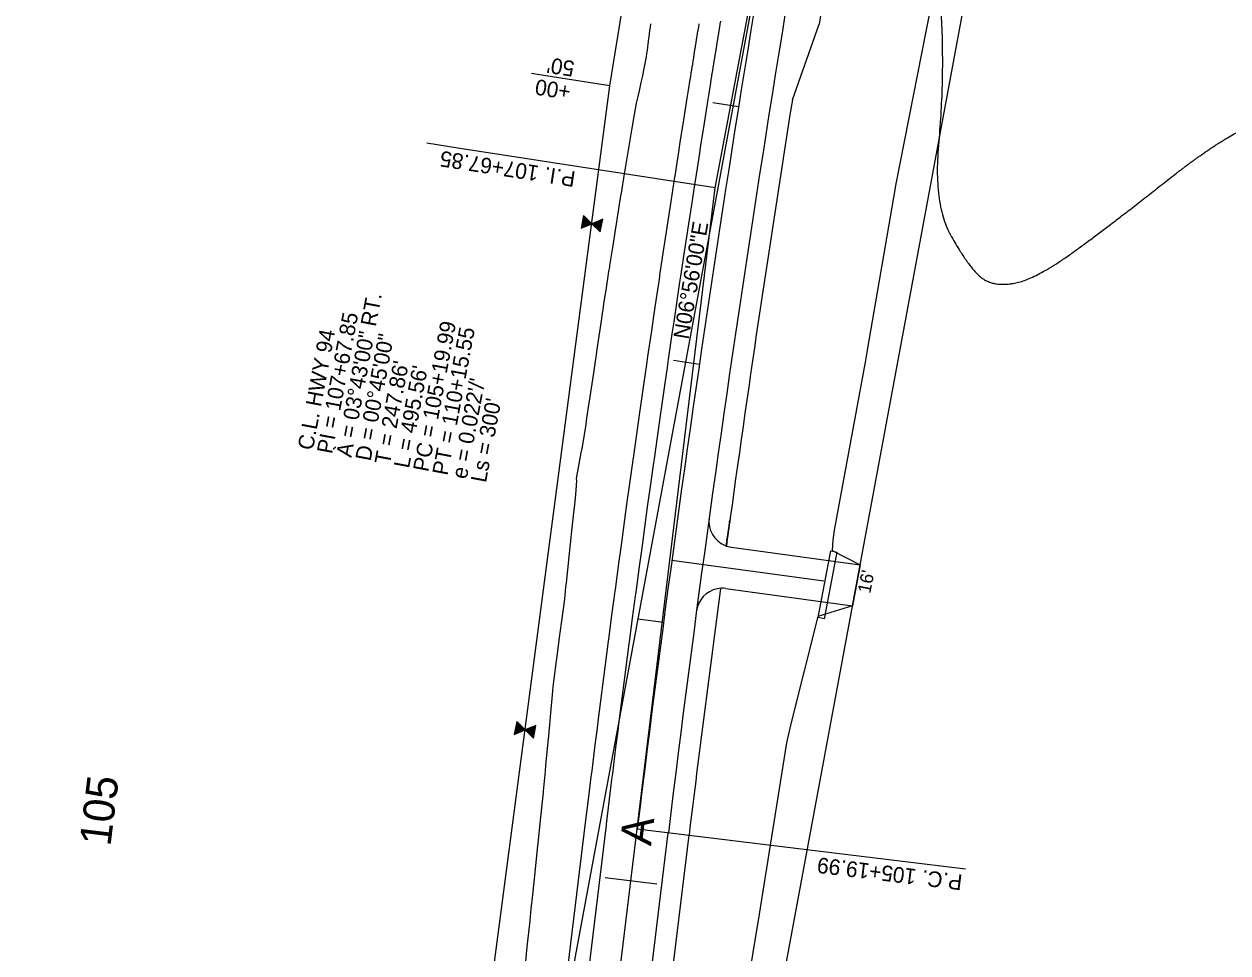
# Model space of a CAD drawing. Extents: x 674098 to 689971, y 764717 to 781049.
# Drawn here: x 688338 to 688800.2, y 765564.3 to 765920.7 of the extents above; entities that cross this region are included whole.
import ezdxf

# ---------------------------------------------------------------- set-up
doc = ezdxf.new("R2010")
doc.units = 0
for name, color, linetype in [('FLOODPLAIN', 7, 'Continuous'), ('R_Drainage Stage 2', 7, 'Continuous'), ('R_Drive Stage 2', 7, 'Continuous'), ('R_Fence', 7, 'Continuous'), ('R_Horz Alg', 7, 'Continuous'), ('R_Horz Alg Annot', 7, 'Continuous'), ('R_Horz Alg Curve Data', 7, 'Continuous'), ('R_Horz Alg Station', 7, 'Continuous'), ('R_Horz Alg Station Annot', 7, 'Continuous'), ('R_No Plot', 7, 'Continuous'), ('R_Proposed Const Limits', 7, 'Continuous'), ('R_Proposed Const Limits Stage 2', 7, 'Continuous'), ('R_Proposed Road', 7, 'Continuous'), ('R_Proposed Road S2', 7, 'Continuous'), ('R_Proposed Shoulder S1', 7, 'Continuous'), ('R_Proposed Shoulder S2', 7, 'Continuous'), ('R_ROW', 7, 'Continuous'), ('R_ROW Annot', 7, 'Continuous'), ('S_EXIST_ROW', 7, 'Continuous')]:
    doc.layers.add(name, color=color, linetype=linetype)

msp = doc.modelspace()

# ---------------------------------------------------------------- linework, layer by layer
at = {"layer": 'FLOODPLAIN'}
msp.add_open_spline([(687720.93, 765952.26), (687778.36, 766010.11), (687818.58, 766026.73), (687865.88, 766035.53), (687900.32, 766027.46), (687971.79, 766010.71), (687996.8, 765994.57), (688033.36, 766007.25), (688051.03, 766027.11), (688052.57, 766065.83), (688149.21, 766117.06), (688189.14, 766131.99), (688217.73, 766125.29), (688254.11, 766123.43), (688329.61, 766125.06), (688414.48, 766126.21), (688456.69, 766120.07), (688534.31, 766092.2), (688588.47, 766053.98), (688667.06, 766003.49), (688675.83, 765962.56), (688689.19, 765943.25), (688691.21, 765898.82), (688686.99, 765851.93), (688700.19, 765828.01), (688709.66, 765819.75), (688726.48, 765822.75), (688756.45, 765844.6), (688793.54, 765873.97), (688815.68, 765885.35), (688838.55, 765872.15), (688859.55, 765848.56), (688852.23, 765830.57), (688864.28, 765797.08), (688875.92, 765781.82), (688895.44, 765777.24), (688920.07, 765784), (688941.19, 765800.55), (688957.82, 765812.32), (689023.63, 765808.54), (689168.4, 765808.74), (689203.62, 765800.49), (689260.93, 765781.46), (689309.41, 765766.74), (689347.39, 765757.84), (689378.08, 765755.12), (689447.63, 765742.59), (689518.73, 765731.75), (689531.07, 765726.17), (689546.85, 765710.38)], degree=2, dxfattribs=at)
at = {"layer": 'R_Drainage Stage 2'}
for p, q in [((688642.8, 765692.99), (688647.71, 765718.52)), ((688645.26, 765692.51), (688650.16, 765718.05)), ((688647.71, 765718.52), (688650.16, 765718.05)), ((688645.26, 765692.51), (688642.8, 765692.99))]:
    msp.add_line(p, q, dxfattribs=at)
at = {"layer": 'R_Drive Stage 2'}
msp.add_line((688656.07, 765697.51), (688658.99, 765713.26), dxfattribs=at)
at = {"layer": 'R_Fence'}
for p, q in [((688552.01, 765843.5), (688552.55, 765842.7)), ((688552.14, 765844.2), (688553.02, 765842.89)), ((688552.28, 765844.89), (688553.49, 765843.09)), ((688552.41, 765845.59), (688553.96, 765843.28)), ((688552.55, 765846.28), (688554.43, 765843.48)), ((688552.68, 765846.97), (688554.9, 765843.68)), ((688553.74, 765846.29), (688555.37, 765843.87)), ((688555.56, 765844.5), (688555.84, 765844.07)), ((688556.32, 765844.27), (688557.37, 765842.7)), ((688556.79, 765844.46), (688559.15, 765840.95)), ((688557.26, 765844.66), (688559.29, 765841.64)), ((688557.73, 765844.85), (688559.42, 765842.34)), ((688558.2, 765845.05), (688559.56, 765843.03)), ((688558.67, 765845.25), (688559.69, 765843.73)), ((688559.14, 765845.44), (688559.83, 765844.42)), ((688559.61, 765845.64), (688559.96, 765845.11)), ((688560.08, 765845.84), (688560.1, 765845.81)), ((688551.87, 765842.81), (688552.08, 765842.5)), ((688526.51, 765649.93), (688527.39, 765648.63)), ((688526.64, 765650.62), (688527.86, 765648.82)), ((688526.78, 765651.32), (688528.33, 765649.02)), ((688526.91, 765652.01), (688528.8, 765649.21)), ((688527.05, 765652.71), (688529.27, 765649.41)), ((688528.11, 765652.03), (688529.74, 765649.61)), ((688529.92, 765650.23), (688530.21, 765649.8)), ((688530.68, 765650), (688531.73, 765648.44)), ((688531.15, 765650.19), (688533.51, 765646.68)), ((688531.62, 765650.39), (688533.65, 765647.38)), ((688532.09, 765650.59), (688533.79, 765648.07)), ((688532.56, 765650.78), (688533.92, 765648.77)), ((688533.03, 765650.98), (688534.06, 765649.46)), ((688533.5, 765651.18), (688534.19, 765650.15)), ((688533.97, 765651.37), (688534.33, 765650.85)), ((688534.45, 765651.57), (688534.46, 765651.54)), ((688526.24, 765648.54), (688526.44, 765648.23)), ((688526.37, 765649.24), (688526.91, 765648.43))]:
    msp.add_line(p, q, dxfattribs=at)
for points in [[(688555.96, 765844.12), (688555.94, 765844.12), (688552.75, 765847.28), (688551.79, 765842.38), (688555.94, 765844.11), (688555.95, 765844.11), (688559.15, 765840.94), (688560.11, 765845.85), (688555.96, 765844.12)], [(688530.32, 765649.85), (688530.3, 765649.85), (688527.11, 765653.02), (688526.15, 765648.11), (688530.3, 765649.84), (688530.32, 765649.84), (688533.51, 765646.67), (688534.47, 765651.58), (688530.32, 765649.85)]]:
    msp.add_lwpolyline(points, dxfattribs=at)
at = {"layer": 'R_Horz Alg'}
for p, q in [((688603.33, 765857.88), (688649.13, 766101.47)), ((688573.4, 765611.83), (688603.33, 765857.88)), ((688510.61, 765095.41), (688573.4, 765611.83))]:
    msp.add_line(p, q, dxfattribs=at)
msp.add_arc((696156.98, 764689.64), 7639.44, 169.35, 173.066667, dxfattribs=at)
msp.add_arc((696156.98, 764689.64), 7639.44, 169.35, 173.066667, dxfattribs=at)
at = {"layer": 'R_Horz Alg Station'}
for points in [[(688602.42, 765890.68), (688612.29, 765889.11)], [(688603.33, 765857.88), (688504.5, 765873.16), (688492.64, 765875)], [(688587.34, 765791.69), (688597.24, 765790.25)], [(688573.56, 765692.51), (688583.48, 765691.2)], [(688573.4, 765611.83), (688699.47, 765596.5)], [(688561.06, 765593.19), (688580.92, 765590.78)]]:
    msp.add_lwpolyline(points, dxfattribs=at)
at = {"layer": 'R_No Plot'}
msp.add_line((688586.66, 765714.99), (688644.96, 765707.09), dxfattribs=at)
at = {"layer": 'R_Proposed Const Limits'}
msp.add_lwpolyline([(688530.31, 765558.21), (688531.17, 765566.61), (688532.2, 765576.55), (688532.68, 765581.18), (688533.23, 765586.5), (688534.27, 765596.45), (688535.08, 765604.15), (688535.31, 765606.4), (688536.38, 765616.33), (688536.38, 765616.34), (688537.35, 765625.83), (688537.4, 765626.34), (688538.11, 765634.03), (688538.33, 765636.35), (688539.26, 765646.36), (688539.38, 765647.63), (688539.77, 765651.75), (688540.2, 765656.37), (688540.86, 765663.35), (688541.15, 765666.38), (688541.47, 765669.47), (688542.39, 765676.36), (688542.75, 765679.03), (688543.64, 765686.33), (688543.75, 765687.11), (688545.09, 765696.28), (688545.51, 765700.03), (688546.01, 765704.75), (688546.16, 765706.27), (688547.25, 765716.27), (688547.68, 765720.27), (688547.77, 765721.11), (688547.9, 765722.45), (688548.27, 765726.27), (688548.89, 765731.98), (688548.91, 765732.27), (688549.35, 765736.27), (688549.74, 765740.15), (688550.17, 765745.39), (688550.06, 765746.32), (688551.88, 765756.22), (688552.17, 765757.78), (688553.58, 765766.13), (688554.08, 765769.47), (688554.95, 765775.35), (688555.06, 765776.07), (688556.52, 765786.02), (688557.33, 765791.39), (688557.56, 765792.95), (688558, 765795.96), (688559.49, 765805.9), (688560.18, 765810.55), (688560.27, 765811.12), (688560.59, 765813.32), (688560.97, 765815.84), (688561.38, 765818.56), (688562.52, 765825.78), (688562.8, 765827.51), (688562.9, 765828.13), (688564.08, 765835.71), (688565.07, 765841.69), (688565.72, 765845.62), (688565.73, 765845.69), (688567.25, 765855.56), (688567.29, 765855.88), (688568.42, 765863.28), (688568.44, 765863.36), (688568.88, 765865.48), (688569.63, 765870.05), (688570.5, 765875.4), (688571.41, 765880.81), (688572.17, 765885.31), (688573.09, 765890.37), (688573.68, 765892.91), (688574.21, 765895.16), (688574.93, 765898.27), (688575.53, 765900.83), (688575.96, 765903.03), (688576.2, 765904.29), (688576.33, 765905), (688576.44, 765905.56), (688576.68, 765906.82), (688576.92, 765908.09), (688577.1, 765909.37), (688577.26, 765910.65), (688577.43, 765911.92), (688577.59, 765913.2), (688577.67, 765913.83), (688577.76, 765914.48), (688577.82, 765914.94), (688577.93, 765915.8), (688578.09, 765917.04), (688578.25, 765918.32), (688578.42, 765919.59), (688578.59, 765920.87)], dxfattribs=at)
at = {"layer": 'R_Proposed Const Limits Stage 2'}
msp.add_lwpolyline([(688739.6, 766170.7), (688739.78, 766170.36), (688733.09, 766125.83), (688723.38, 766100.71), (688722.97, 766099.48), (688703.6, 766016.4), (688703.35, 766015.16), (688684.44, 765919.13), (688684.2, 765917.9), (688672.72, 765859.42), (688671.72, 765854.17), (688661.69, 765795.57), (688660.89, 765791), (688648.95, 765726.45), (688648.45, 765722.64), (688648.26, 765718.66), (688658.99, 765713.26), (688656.07, 765697.51), (688642.73, 765693.37), (688632.18, 765651.68), (688630.7, 765644.89), (688619.68, 765575.99), (688618.83, 765570.71), (688614.85, 765546.36)], dxfattribs=at)
at = {"layer": 'R_Proposed Road'}
for points in [[(688561.57, 765613.69), (688562.73, 765623.22), (688563.68, 765630.86), (688563.96, 765633.16), (688565.2, 765643.1), (688565.88, 765648.45), (688566.46, 765653.03), (688567.73, 765662.97), (688568.12, 765666.03), (688569.01, 765672.9), (688570.3, 765682.83), (688570.4, 765683.61), (688571.61, 765692.76), (688572.73, 765701.18), (688572.93, 765702.69), (688574.26, 765712.62), (688575.09, 765718.75), (688575.61, 765722.54), (688576.96, 765732.47), (688577.49, 765736.31), (688578.34, 765742.39), (688579.72, 765752.31), (688579.94, 765753.87), (688581.12, 765762.23), (688582.43, 765771.42), (688582.53, 765772.14), (688583.95, 765782.05), (688584.95, 765788.97), (688585.39, 765791.97), (688586.84, 765801.88), (688587.52, 765806.51), (688588.3, 765811.79), (688589.78, 765821.69), (688590.13, 765824.04), (688590.62, 765827.35), (688591.26, 765831.6), (688592.76, 765841.5), (688592.78, 765841.57), (688594.28, 765851.4), (688595.46, 765859.09), (688595.48, 765859.17), (688595.81, 765861.3), (688597.35, 765871.19), (688597.68, 765873.31), (688598.19, 765876.6), (688598.9, 765881.09), (688600.47, 765890.98), (688600.96, 765894.11), (688601.62, 765898.2), (688601.81, 765899.38), (688602, 765900.57), (688602.04, 765900.87), (688602.19, 765901.75), (688602.38, 765902.93), (688602.57, 765904.11), (688602.76, 765905.29), (688602.95, 765906.48), (688603.14, 765907.66), (688603.33, 765908.84), (688603.52, 765910.02), (688603.64, 765910.76), (688603.71, 765911.2), (688603.77, 765911.61), (688603.9, 765912.39), (688604.09, 765913.57), (688604.28, 765914.75), (688604.47, 765915.93), (688604.67, 765917.11), (688604.86, 765918.29), (688605.05, 765919.48), (688605.24, 765920.65), (688605.24, 765920.66), (688605.44, 765921.84)], [(688499.6, 765096.98), (688510.82, 765196.35), (688553.07, 765543.79), (688561.52, 765613.28), (688561.57, 765613.69)]]:
    msp.add_lwpolyline(points, dxfattribs=at)
msp.add_arc((696156.98, 764689.64), 7627.44, 169.35, 173.066667, dxfattribs=at)
at = {"layer": 'R_Proposed Road S2'}
for p, q in [((688609.56, 765719.96), (688658.99, 765713.26)), ((688607.41, 765704.11), (688656.07, 765697.51))]:
    msp.add_line(p, q, dxfattribs=at)
msp.add_lwpolyline([(688522.17, 765094.24), (688534.59, 765193.47), (688585.28, 765610.38)], dxfattribs=at)
for centre, start, end in [((688610.9, 765729.87), 172.1512, 247.63), ((688610.9, 765729.87), 247.63, 262.2866), ((688606.07, 765694.2), 101.9504, 172.422), ((688606.07, 765694.2), 82.2866, 101.9504)]:
    msp.add_arc(centre, 10, start, end, dxfattribs=at)
at = {"layer": 'R_Proposed Shoulder S1'}
msp.add_line((688632.95, 765891.66), (688643.22, 765920.72), dxfattribs=at)
msp.add_lwpolyline([(688545.12, 765544.76), (688553.57, 765614.24), (688554.79, 765624.2), (688555.73, 765631.84), (688556.02, 765634.15), (688557.26, 765644.1), (688557.93, 765649.45), (688558.52, 765654.04), (688559.78, 765663.99), (688560.18, 765667.05), (688561.07, 765673.93), (688562.36, 765683.87), (688562.46, 765684.65), (688563.67, 765693.81), (688564.79, 765702.24), (688564.99, 765703.75), (688566.32, 765713.69), (688567.16, 765719.83), (688567.67, 765723.63), (688569.03, 765733.56), (688569.56, 765737.41), (688570.4, 765743.49), (688571.79, 765753.42), (688572.01, 765754.99), (688573.19, 765763.35), (688574.5, 765772.55), (688574.6, 765773.28), (688576.03, 765783.2), (688577.03, 765790.12), (688577.46, 765793.12), (688578.92, 765803.04), (688579.6, 765807.68), (688580.38, 765812.96), (688581.86, 765822.88), (688582.21, 765825.23), (688582.71, 765828.54), (688583.35, 765832.79), (688584.85, 765842.71), (688584.86, 765842.77), (688586.36, 765852.62), (688587.55, 765860.31), (688587.56, 765860.39), (688587.89, 765862.52), (688589.44, 765872.43), (688589.77, 765874.55), (688590.28, 765877.84), (688590.99, 765882.34), (688592.56, 765892.24), (688593.06, 765895.37), (688593.71, 765899.47), (688593.9, 765900.65), (688594.09, 765901.83), (688594.14, 765902.14), (688594.28, 765903.02), (688594.47, 765904.2), (688594.66, 765905.38), (688594.85, 765906.57), (688595.04, 765907.75), (688595.23, 765908.93), (688595.42, 765910.12), (688595.61, 765911.3), (688595.73, 765912.04), (688595.8, 765912.48), (688595.87, 765912.89), (688596, 765913.67), (688596.19, 765914.85), (688596.38, 765916.03), (688596.57, 765917.21), (688596.76, 765918.4), (688596.96, 765919.58), (688597.15, 765920.76)], dxfattribs=at)
for radius, start, end in [(7613.94, 168.743915, 170.695122), (7619.44, 170.923251, 172.143198), (7619.44, 172.143198, 172.224821)]:
    msp.add_arc((696156.98, 764689.64), radius, start, end, dxfattribs=at)
at = {"layer": 'R_Proposed Shoulder S2'}
for points in [[(688607.56, 765720.46), (688608.61, 765728.13), (688608.92, 765730.43)], [(688522.17, 765094.24), (688542.53, 765192.51), (688543.73, 765202.44), (688561.86, 765351.53), (688593.26, 765609.41)]]:
    msp.add_lwpolyline(points, dxfattribs=at)
msp.add_arc((696156.98, 764689.64), 7619.44, 172.34828, 173.066667, dxfattribs=at)
at = {"layer": 'R_ROW'}
for p, q in [((688562.91, 765896.96), (688607.18, 766175.98)), ((688495.22, 765383.1), (688562.91, 765896.96))]:
    msp.add_line(p, q, dxfattribs=at)
at = {"layer": 'R_ROW Annot'}
msp.add_lwpolyline([(688562.91, 765896.96), (688538.22, 765900.88), (688532.79, 765901.75)], dxfattribs=at)
at = {"layer": 'S_EXIST_ROW'}
for p, q in [((688514.64, 765373.87), (688661.62, 766165.87)), ((688571.89, 765243.87), (688740.27, 766151.28))]:
    msp.add_line(p, q, dxfattribs=at)

# ---------------------------------------------------------------- texts
at = {"layer": 'R_Horz Alg'}
for rotation, p in [(83.0667, (688578.64, 765605.15)), (83.3627, (688578.67, 765605.17))]:
    msp.add_text('A', height=12, rotation=rotation, dxfattribs=at).set_placement(p)
at = {"layer": 'R_Horz Alg Annot'}
msp.add_text('N06%%d56\'00"E', height=6, rotation=80.3613, dxfattribs=at).set_placement((688593.1, 765799.49))
at = {"layer": 'R_Horz Alg Curve Data'}
for s, p in [('À = 03%%d43\'00" RT. ', (688463.59, 765754.15)), ('PI = 107+67.85', (688456.21, 765755.53)), ('PC = 105+19.99', (688493.12, 765748.62)), ('C.L. HWY 94 ', (688448.82, 765756.91)), ('D = 00%%d45\'00"', (688470.97, 765752.77)), ('PT = 110+15.55', (688500.51, 765747.24)), ("T = 247.86'", (688478.36, 765751.39)), ("L = 495.56'", (688485.74, 765750)), ("e = 0.022'/'", (688507.89, 765745.86)), ("Ls = 300'", (688515.28, 765744.48))]:
    msp.add_text(s, height=6, rotation=79.4045, dxfattribs=at).set_placement(p)
at = {"layer": 'R_Horz Alg Station Annot'}
for s, height, rotation, p in [('P.I. 107+67.85', 6, 171.2083, (688549.98, 765864.1)), ('105', 12, 83.0667, (688371.1, 765604.96)), ('P.C. 105+19.99', 6, 173.0667, (688698.47, 765594.23))]:
    msp.add_text(s, height=height, rotation=rotation, dxfattribs=at).set_placement(p)
at = {"layer": 'R_Proposed Road S2'}
msp.add_text("16'", height=5, rotation=78.7196, dxfattribs=at).set_placement((688662.83, 765702.01))
at = {"layer": 'R_ROW Annot'}
for s, p in [("50'", (688549.59, 765906.4)), ('+00', (688548.18, 765897.51))]:
    msp.add_text(s, height=6, rotation=170.9666, dxfattribs=at).set_placement(p)

doc.saveas('drawing.dxf')
